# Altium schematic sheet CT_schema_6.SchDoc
size 297 x 173 mm
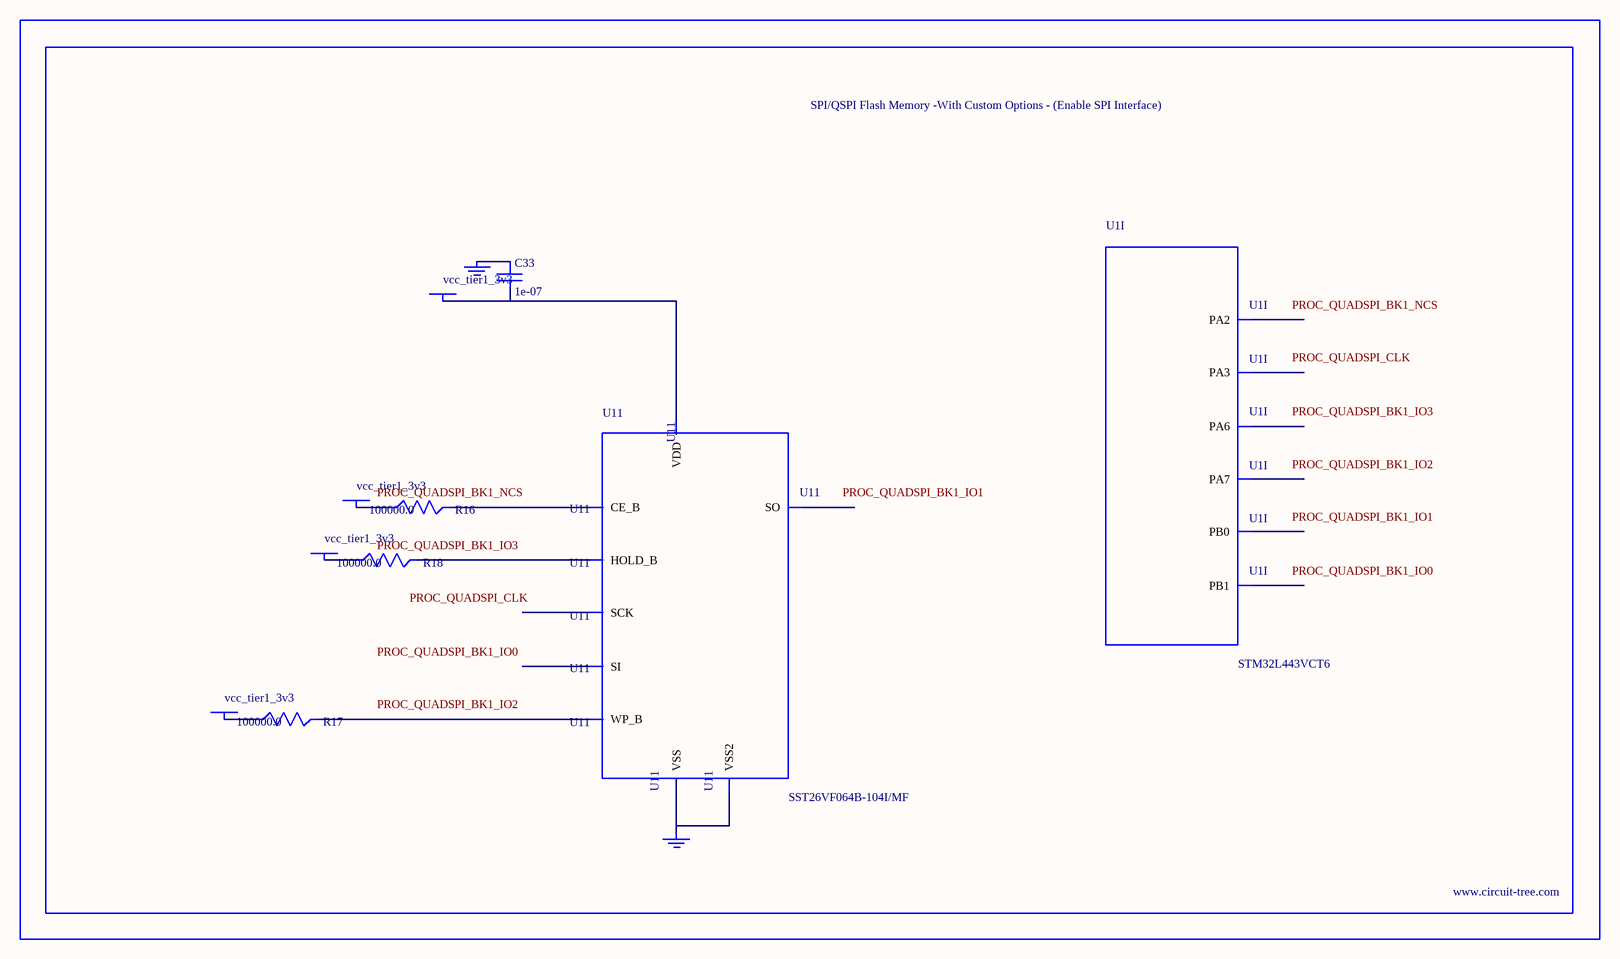
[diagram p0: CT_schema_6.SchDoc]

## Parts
BORDER5  (no value)
C33  1e-07  [C0402]
GND_INSTANCE_5_0  (no value)
GND_INSTANCE_5_1  (no value)
POWER_INSTANCE_5_0  vcc_tier1_3v3
POWER_INSTANCE_5_1  vcc_tier1_3v3
POWER_INSTANCE_5_2  vcc_tier1_3v3
POWER_INSTANCE_5_3  vcc_tier1_3v3
R16  100000.0  [R0603]
R17  100000.0  [R0603]
R18  100000.0  [R0603]
U1  STM32L443VCT6  [LQFP100]  (part I of 9)
U11  SST26VF064B-104I/MF  [WFDN-8]

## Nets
NetC33_1: C33.1 GND_INSTANCE_5_0.0(GND)
NetC33_2: C33.2 POWER_INSTANCE_5_3.0(PWR) U11.8(VDD)
NetGND_INSTANCE_5_1_0: GND_INSTANCE_5_1.0(GND) U11.4(VSS) U11.9(VSS2)
NetPOWER_INSTANCE_5_0_0: POWER_INSTANCE_5_0.0(PWR) R16.1
NetPOWER_INSTANCE_5_1_0: POWER_INSTANCE_5_1.0(PWR) R17.1
NetPOWER_INSTANCE_5_2_0: POWER_INSTANCE_5_2.0(PWR) R18.1
NetR16_2: R16.2 U11.1(CE_B)
NetR17_2: R17.2 U11.3(WP_B)
NetR18_2: R18.2 U11.7(HOLD_B)

Not connected (* = marked no-connect by the designer): U1 25(PA2) 26(PA3) 31(PA6) 32(PA7) 35(PB0) 36(PB1); U11 2(SO) 5(SI) 6(SCK)

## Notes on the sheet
- Labels drawn without touching a wire or pin: PROC_QUADSPI_BK1_IO0, PROC_QUADSPI_BK1_IO1, PROC_QUADSPI_BK1_IO2, PROC_QUADSPI_BK1_IO3, PROC_QUADSPI_BK1_NCS, PROC_QUADSPI_CLK

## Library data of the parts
BORDER5 = BORDER_PAGE5
C33 = C0402C104K3RACTU
GND_INSTANCE_5_0 GND_INSTANCE_5_1 = GND
POWER_INSTANCE_5_0-POWER_INSTANCE_5_3 = PWR
R16-R18 = RC0603JR-07100KL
